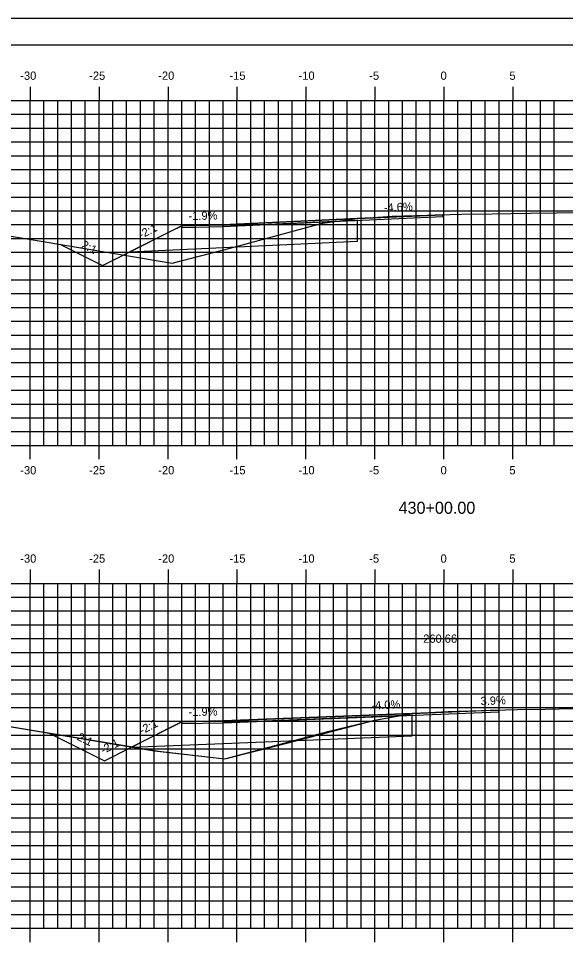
# Model space of a CAD drawing. Extents: x 1168600 to 1177589, y 610178 to 611246.
# Drawn here: x 1175598.1 to 1175637.7, y 610943.3 to 611010.5 of the extents above; entities that cross this region are included whole.
import ezdxf

# ---------------------------------------------------------------- set-up
doc = ezdxf.new("R2010")
doc.units = 0
for name, color, linetype in [('_Construction', 7, 'Continuous'), ('_Station Equation', 7, 'Continuous'), ('ANNOTATION', 7, 'Continuous'), ('D_Roadway_Centerline_Text', 7, 'Continuous'), ('D_Roadway_Edge_TW', 7, 'Continuous'), ('D_Roadway_SubGrade', 7, 'Continuous'), ('D_Slope_Direction', 7, 'Continuous'), ('D_Text_Standard', 7, 'Continuous'), ('H_V ANNOTATION', 7, 'Continuous'), ('MAJOR', 7, 'Continuous'), ('MATCH LINES', 7, 'Continuous'), ('MINOR', 7, 'Continuous')]:
    doc.layers.add(name, color=color, linetype=linetype)

msp = doc.modelspace()

# ---------------------------------------------------------------- linework, layer by layer
at = {"layer": '_Construction'}
msp.add_line((1175713.907, 611008.596), (1175553.907, 611008.596), dxfattribs=at)
msp.add_lwpolyline([(1175545.813, 610900.537), (1175715.813, 610900.537), (1175715.813, 611010.537), (1175545.813, 611010.537)], close=True, dxfattribs=at)
at = {"layer": '_Station Equation'}
for points in [[(1175558.906, 610999.472), (1175561.135, 610999.342), (1175570.673, 610998.545), (1175591.003, 610995.85), (1175598.702, 610994.577), (1175609.218, 610992.798), (1175613.404, 610993.903), (1175620.107, 610995.709), (1175622.451, 610996.017), (1175622.653, 610996.033), (1175623.778, 610996.113), (1175625.164, 610996.209), (1175627.75, 610996.287), (1175630.178, 610996.354), (1175632.416, 610996.39), (1175635.192, 610996.436), (1175637.081, 610996.46), (1175640.207, 610996.5)], [(1175558.906, 610999.472), (1175561.135, 610999.342), (1175570.437, 610998.097), (1175591.003, 610995.85), (1175598.703, 610994.577), (1175609.218, 610992.798), (1175613.404, 610993.903), (1175620.107, 610995.709), (1175622.452, 610996.017), (1175622.653, 610996.033), (1175623.777, 610996.113), (1175625.164, 610996.209), (1175627.749, 610996.287), (1175630.178, 610996.354), (1175632.415, 610996.39), (1175635.192, 610996.436), (1175637.08, 610996.46), (1175640.207, 610996.5)], [(1175558.906, 610963.059), (1175560.503, 610962.973), (1175582.409, 610961.101), (1175591.481, 610960.219), (1175608.214, 610957.43), (1175613.021, 610956.887), (1175617.624, 610958.04), (1175623.889, 610959.689), (1175626.561, 610960.16), (1175626.605, 610960.167), (1175626.71, 610960.174), (1175626.905, 610960.184), (1175629.22, 610960.311), (1175631.641, 610960.379), (1175634.239, 610960.45), (1175636.259, 610960.487), (1175639.258, 610960.542)], [(1175558.906, 610963.054), (1175560.503, 610962.973), (1175585.574, 610960.888), (1175591.481, 610960.219), (1175607.923, 610957.463), (1175613.021, 610956.887), (1175620.598, 610958.89), (1175623.888, 610959.689), (1175625.664, 610960.003), (1175626.563, 610960.16), (1175626.605, 610960.167), (1175626.71, 610960.174), (1175626.906, 610960.184), (1175629.22, 610960.311), (1175631.641, 610960.379), (1175634.239, 610960.45), (1175636.259, 610960.487), (1175639.258, 610960.542)]]:
    msp.add_lwpolyline(points, dxfattribs=at)
at = {"layer": 'D_Roadway_Edge_TW'}
for points in [[(1175628.834, 610996.317), (1175622.653, 610996.032), (1175612.906, 610995.577), (1175609.914, 610995.521), (1175609.914, 610995.396), (1175612.906, 610995.452), (1175628.834, 610996.192)], [(1175628.834, 610996.317), (1175622.653, 610996.032), (1175612.906, 610995.577), (1175609.914, 610995.521), (1175609.914, 610995.396), (1175612.906, 610995.452), (1175628.834, 610996.192)], [(1175632.882, 610960.413), (1175626.605, 610960.167), (1175612.906, 610959.623), (1175609.917, 610959.567), (1175609.917, 610959.442), (1175612.906, 610959.498), (1175632.882, 610960.288)], [(1175632.882, 610960.413), (1175626.605, 610960.167), (1175612.906, 610959.623), (1175609.917, 610959.567), (1175609.917, 610959.442), (1175612.906, 610959.498), (1175632.882, 610960.288)]]:
    msp.add_lwpolyline(points, close=True, dxfattribs=at)
for points in [[(1175628.834, 610996.317), (1175622.653, 610996.032), (1175612.906, 610995.577), (1175612.906, 610995.452), (1175628.834, 610996.192), (1175628.834, 610996.317)], [(1175628.834, 610996.317), (1175622.653, 610996.032), (1175612.906, 610995.577), (1175612.906, 610995.452), (1175628.834, 610996.192), (1175628.834, 610996.317)], [(1175632.882, 610960.413), (1175626.605, 610960.167), (1175612.906, 610959.623), (1175612.906, 610959.498), (1175632.882, 610960.288), (1175632.882, 610960.413)], [(1175632.882, 610960.413), (1175626.605, 610960.167), (1175612.906, 610959.623), (1175612.906, 610959.498), (1175632.882, 610960.288), (1175632.882, 610960.413)]]:
    msp.add_lwpolyline(points, dxfattribs=at)
at = {"layer": 'D_Roadway_SubGrade'}
for points in [[(1175612.906, 610995.577), (1175609.914, 610995.521), (1175606.143, 610993.635), (1175612.906, 610993.952), (1175622.653, 610994.407), (1175622.653, 610995.907), (1175612.906, 610995.452)], [(1175612.906, 610995.577), (1175609.914, 610995.521), (1175606.143, 610993.635), (1175612.906, 610993.952), (1175622.653, 610994.407), (1175622.653, 610995.907), (1175612.906, 610995.452)], [(1175612.906, 610959.623), (1175609.917, 610959.567), (1175606.25, 610957.731), (1175612.906, 610957.998), (1175626.605, 610958.542), (1175626.605, 610960.042), (1175612.906, 610959.498)], [(1175612.906, 610959.623), (1175609.917, 610959.567), (1175606.25, 610957.731), (1175612.906, 610957.998), (1175626.605, 610958.542), (1175626.605, 610960.042), (1175612.906, 610959.498)]]:
    msp.add_lwpolyline(points, close=True, dxfattribs=at)
at = {"layer": 'D_Slope_Direction'}
for points in [[(1175612.906, 610995.577), (1175609.914, 610995.521)], [(1175612.906, 610995.577), (1175609.914, 610995.521)], [(1175612.906, 610959.623), (1175609.917, 610959.567)], [(1175612.906, 610959.623), (1175609.917, 610959.567)]]:
    msp.add_lwpolyline(points, dxfattribs=at)
at = {"layer": 'D_Text_Standard'}
for points in [[(1175601.057, 610994.179), (1175604.144, 610992.635), (1175606.143, 610993.635), (1175609.12, 610995.124), (1175609.914, 610995.521), (1175612.761, 610995.574), (1175612.906, 610995.577), (1175613.337, 610995.597), (1175622.653, 610996.032), (1175627.171, 610996.24), (1175628.834, 610996.317)], [(1175600.29, 610958.742), (1175604.307, 610956.734), (1175606.25, 610957.731), (1175607.647, 610958.431), (1175609.917, 610959.567), (1175611.863, 610959.604), (1175612.906, 610959.623), (1175617.326, 610959.799), (1175626.605, 610960.167), (1175632.373, 610960.393), (1175632.882, 610960.413)]]:
    msp.add_lwpolyline(points, dxfattribs=at)
at = {"layer": 'MAJOR'}
for p, q in [((1175598.906, 611005.598), (1175598.906, 611004.596)), ((1175603.906, 611005.598), (1175603.906, 611004.596)), ((1175608.906, 611005.598), (1175608.906, 611004.596)), ((1175613.906, 611005.598), (1175613.906, 611004.596)), ((1175618.906, 611005.598), (1175618.906, 611004.596)), ((1175623.906, 611005.598), (1175623.906, 611004.596)), ((1175628.906, 611005.598), (1175628.906, 611004.596)), ((1175633.906, 611005.598), (1175633.906, 611004.596)), ((1175558.906, 611004.596), (1175698.906, 611004.596)), ((1175558.906, 611004.596), (1175698.906, 611004.596)), ((1175598.906, 610979.596), (1175598.906, 611004.596)), ((1175603.906, 610979.596), (1175603.906, 611004.596)), ((1175608.906, 610979.596), (1175608.906, 611004.596)), ((1175613.906, 610979.596), (1175613.906, 611004.596)), ((1175618.906, 610979.596), (1175618.906, 611004.596)), ((1175623.906, 610979.596), (1175623.906, 611004.596)), ((1175628.906, 610979.596), (1175628.906, 611004.596)), ((1175633.906, 610979.596), (1175633.906, 611004.596)), ((1175558.906, 610999.596), (1175698.906, 610999.596)), ((1175558.906, 610994.596), (1175698.906, 610994.596)), ((1175558.906, 610989.596), (1175698.906, 610989.596)), ((1175558.906, 610984.596), (1175698.906, 610984.596)), ((1175558.906, 610979.596), (1175698.906, 610979.596)), ((1175558.906, 610979.596), (1175698.906, 610979.596)), ((1175598.906, 610978.594), (1175598.906, 610979.596)), ((1175603.906, 610978.594), (1175603.906, 610979.596)), ((1175608.906, 610978.594), (1175608.906, 610979.596)), ((1175613.906, 610978.594), (1175613.906, 610979.596)), ((1175618.906, 610978.594), (1175618.906, 610979.596)), ((1175623.906, 610978.594), (1175623.906, 610979.596)), ((1175628.906, 610978.594), (1175628.906, 610979.596)), ((1175633.906, 610978.594), (1175633.906, 610979.596)), ((1175598.906, 610970.598), (1175598.906, 610969.596)), ((1175603.906, 610970.598), (1175603.906, 610969.596)), ((1175608.906, 610970.598), (1175608.906, 610969.596)), ((1175613.906, 610970.598), (1175613.906, 610969.596)), ((1175618.906, 610970.598), (1175618.906, 610969.596)), ((1175623.906, 610970.598), (1175623.906, 610969.596)), ((1175628.906, 610970.598), (1175628.906, 610969.596)), ((1175633.906, 610970.598), (1175633.906, 610969.596)), ((1175558.906, 610969.596), (1175698.906, 610969.596)), ((1175558.906, 610969.596), (1175698.906, 610969.596)), ((1175598.906, 610944.596), (1175598.906, 610969.596)), ((1175603.906, 610944.596), (1175603.906, 610969.596)), ((1175608.906, 610944.596), (1175608.906, 610969.596)), ((1175613.906, 610944.596), (1175613.906, 610969.596)), ((1175618.906, 610944.596), (1175618.906, 610969.596)), ((1175623.906, 610944.596), (1175623.906, 610969.596)), ((1175628.906, 610944.596), (1175628.906, 610969.596)), ((1175633.906, 610944.596), (1175633.906, 610969.596)), ((1175558.906, 610964.596), (1175698.906, 610964.596)), ((1175558.906, 610959.596), (1175698.906, 610959.596)), ((1175558.906, 610954.596), (1175698.906, 610954.596)), ((1175558.906, 610949.596), (1175698.906, 610949.596)), ((1175558.906, 610944.596), (1175698.906, 610944.596)), ((1175558.906, 610944.596), (1175698.906, 610944.596)), ((1175598.906, 610943.594), (1175598.906, 610944.596)), ((1175603.906, 610943.594), (1175603.906, 610944.596)), ((1175608.906, 610943.594), (1175608.906, 610944.596)), ((1175613.906, 610943.594), (1175613.906, 610944.596)), ((1175618.906, 610943.594), (1175618.906, 610944.596)), ((1175623.906, 610943.594), (1175623.906, 610944.596)), ((1175628.906, 610943.594), (1175628.906, 610944.596)), ((1175633.906, 610943.594), (1175633.906, 610944.596))]:
    msp.add_line(p, q, dxfattribs=at)
at = {"layer": 'MATCH LINES'}
for points in [[(1175612.906, 610995.577), (1175612.906, 610995.452)], [(1175612.906, 610995.577), (1175612.906, 610995.452)], [(1175612.906, 610959.623), (1175612.906, 610959.498)], [(1175612.906, 610959.623), (1175612.906, 610959.498)]]:
    msp.add_lwpolyline(points, dxfattribs=at)
at = {"layer": 'MINOR'}
for p, q in [((1175599.906, 610979.596), (1175599.906, 611004.596)), ((1175600.906, 610979.596), (1175600.906, 611004.596)), ((1175601.906, 610979.596), (1175601.906, 611004.596)), ((1175602.906, 610979.596), (1175602.906, 611004.596)), ((1175604.906, 610979.596), (1175604.906, 611004.596)), ((1175605.906, 610979.596), (1175605.906, 611004.596)), ((1175606.906, 610979.596), (1175606.906, 611004.596)), ((1175607.906, 610979.596), (1175607.906, 611004.596)), ((1175609.906, 610979.596), (1175609.906, 611004.596)), ((1175610.906, 610979.596), (1175610.906, 611004.596)), ((1175611.906, 610979.596), (1175611.906, 611004.596)), ((1175612.906, 610979.596), (1175612.906, 611004.596)), ((1175614.906, 610979.596), (1175614.906, 611004.596)), ((1175615.906, 610979.596), (1175615.906, 611004.596)), ((1175616.906, 610979.596), (1175616.906, 611004.596)), ((1175617.906, 610979.596), (1175617.906, 611004.596)), ((1175619.906, 610979.596), (1175619.906, 611004.596)), ((1175620.906, 610979.596), (1175620.906, 611004.596)), ((1175621.906, 610979.596), (1175621.906, 611004.596)), ((1175622.906, 610979.596), (1175622.906, 611004.596)), ((1175624.906, 610979.596), (1175624.906, 611004.596)), ((1175625.906, 610979.596), (1175625.906, 611004.596)), ((1175626.906, 610979.596), (1175626.906, 611004.596)), ((1175627.906, 610979.596), (1175627.906, 611004.596)), ((1175629.906, 610979.596), (1175629.906, 611004.596)), ((1175630.906, 610979.596), (1175630.906, 611004.596)), ((1175631.906, 610979.596), (1175631.906, 611004.596)), ((1175632.906, 610979.596), (1175632.906, 611004.596)), ((1175634.906, 610979.596), (1175634.906, 611004.596)), ((1175635.906, 610979.596), (1175635.906, 611004.596)), ((1175636.906, 610979.596), (1175636.906, 611004.596)), ((1175558.906, 611003.596), (1175698.906, 611003.596)), ((1175558.906, 611002.596), (1175698.906, 611002.596)), ((1175558.906, 611001.596), (1175698.906, 611001.596)), ((1175558.906, 611000.596), (1175698.906, 611000.596)), ((1175558.906, 610998.596), (1175698.906, 610998.596)), ((1175558.906, 610997.596), (1175698.906, 610997.596)), ((1175558.906, 610996.596), (1175698.906, 610996.596)), ((1175558.906, 610995.596), (1175698.906, 610995.596)), ((1175558.906, 610993.596), (1175698.906, 610993.596)), ((1175558.906, 610992.596), (1175698.906, 610992.596)), ((1175558.906, 610991.596), (1175698.906, 610991.596)), ((1175558.906, 610990.596), (1175698.906, 610990.596)), ((1175558.906, 610988.596), (1175698.906, 610988.596)), ((1175558.906, 610987.596), (1175698.906, 610987.596)), ((1175558.906, 610986.596), (1175698.906, 610986.596)), ((1175558.906, 610985.596), (1175698.906, 610985.596)), ((1175558.906, 610983.596), (1175698.906, 610983.596)), ((1175558.906, 610982.596), (1175698.906, 610982.596)), ((1175558.906, 610981.596), (1175698.906, 610981.596)), ((1175558.906, 610980.596), (1175698.906, 610980.596)), ((1175599.906, 610944.596), (1175599.906, 610969.596)), ((1175600.906, 610944.596), (1175600.906, 610969.596)), ((1175601.906, 610944.596), (1175601.906, 610969.596)), ((1175602.906, 610944.596), (1175602.906, 610969.596)), ((1175604.906, 610944.596), (1175604.906, 610969.596)), ((1175605.906, 610944.596), (1175605.906, 610969.596)), ((1175606.906, 610944.596), (1175606.906, 610969.596)), ((1175607.906, 610944.596), (1175607.906, 610969.596)), ((1175609.906, 610944.596), (1175609.906, 610969.596)), ((1175610.906, 610944.596), (1175610.906, 610969.596)), ((1175611.906, 610944.596), (1175611.906, 610969.596)), ((1175612.906, 610944.596), (1175612.906, 610969.596)), ((1175614.906, 610944.596), (1175614.906, 610969.596)), ((1175615.906, 610944.596), (1175615.906, 610969.596)), ((1175616.906, 610944.596), (1175616.906, 610969.596)), ((1175617.906, 610944.596), (1175617.906, 610969.596)), ((1175619.906, 610944.596), (1175619.906, 610969.596)), ((1175620.906, 610944.596), (1175620.906, 610969.596)), ((1175621.906, 610944.596), (1175621.906, 610969.596)), ((1175622.906, 610944.596), (1175622.906, 610969.596)), ((1175624.906, 610944.596), (1175624.906, 610969.596)), ((1175625.906, 610944.596), (1175625.906, 610969.596)), ((1175626.906, 610944.596), (1175626.906, 610969.596)), ((1175627.906, 610944.596), (1175627.906, 610969.596)), ((1175629.906, 610944.596), (1175629.906, 610969.596)), ((1175630.906, 610944.596), (1175630.906, 610969.596)), ((1175631.906, 610944.596), (1175631.906, 610969.596)), ((1175632.906, 610944.596), (1175632.906, 610969.596)), ((1175634.906, 610944.596), (1175634.906, 610969.596)), ((1175635.906, 610944.596), (1175635.906, 610969.596)), ((1175636.906, 610944.596), (1175636.906, 610969.596)), ((1175558.906, 610968.596), (1175698.906, 610968.596)), ((1175558.906, 610967.596), (1175698.906, 610967.596)), ((1175558.906, 610966.596), (1175698.906, 610966.596)), ((1175558.906, 610965.596), (1175698.906, 610965.596)), ((1175558.906, 610963.596), (1175698.906, 610963.596)), ((1175558.906, 610962.596), (1175698.906, 610962.596)), ((1175558.906, 610961.596), (1175698.906, 610961.596)), ((1175558.906, 610960.596), (1175698.906, 610960.596)), ((1175558.906, 610958.596), (1175698.906, 610958.596)), ((1175558.906, 610957.596), (1175698.906, 610957.596)), ((1175558.906, 610956.596), (1175698.906, 610956.596)), ((1175558.906, 610955.596), (1175698.906, 610955.596)), ((1175558.906, 610953.596), (1175698.906, 610953.596)), ((1175558.906, 610952.596), (1175698.906, 610952.596)), ((1175558.906, 610951.596), (1175698.906, 610951.596)), ((1175558.906, 610950.596), (1175698.906, 610950.596)), ((1175558.906, 610948.596), (1175698.906, 610948.596)), ((1175558.906, 610947.596), (1175698.906, 610947.596)), ((1175558.906, 610946.596), (1175698.906, 610946.596)), ((1175558.906, 610945.596), (1175698.906, 610945.596))]:
    msp.add_line(p, q, dxfattribs=at)

# ---------------------------------------------------------------- texts
at = {"layer": 'ANNOTATION'}
for s, rotation, p in [('-4.6%', 2.63741, (1175624.564, 610996.522)), ('-1.9%', 1.07154, (1175610.397, 610995.93)), ('-2:1', 26.56661, (1175606.958, 610994.561)), ('2:1', 333.43495, (1175602.568, 610993.942)), ('-4.0%', 2.26023, (1175623.666, 610960.45)), ('3.9%', 2.26142, (1175631.578, 610960.763)), ('-1.9%', 1.07289, (1175610.398, 610959.976)), ('-2:1', 26.59525, (1175607.012, 610958.631)), ('2:1', 333.43495, (1175602.265, 610958.272)), ('-2:1', 27.17394, (1175604.201, 610957.204))]:
    msp.add_text(s, height=0.6, rotation=rotation, dxfattribs=at).set_placement(p)
at = {"layer": 'D_Roadway_Centerline_Text'}
msp.add_text('260.66', height=0.6, dxfattribs=at).set_placement((1175627.408, 610965.289))
at = {"layer": 'H_V ANNOTATION'}
for s, height, p in [('-30', 0.6, (1175598.195, 611006.096)), ('-25', 0.6, (1175603.192, 611006.096)), ('-20', 0.6, (1175608.2, 611006.096)), ('-15', 0.6, (1175613.363, 611006.096)), ('-10', 0.6, (1175618.371, 611006.096)), ('-5', 0.6, (1175623.497, 611006.096)), ('0', 0.6, (1175628.665, 611006.096)), ('5', 0.6, (1175633.657, 611006.096)), ('-30', 0.6, (1175598.195, 610977.496)), ('-25', 0.6, (1175603.192, 610977.496)), ('-20', 0.6, (1175608.2, 610977.496)), ('-15', 0.6, (1175613.363, 610977.496)), ('-10', 0.6, (1175618.371, 610977.496)), ('-5', 0.6, (1175623.497, 610977.496)), ('0', 0.6, (1175628.665, 610977.496)), ('5', 0.6, (1175633.657, 610977.496)), ('430+00.00', 0.875, (1175625.621, 610974.639)), ('-30', 0.6, (1175598.195, 610971.096)), ('-25', 0.6, (1175603.192, 610971.096)), ('-20', 0.6, (1175608.2, 610971.096)), ('-15', 0.6, (1175613.363, 610971.096)), ('-10', 0.6, (1175618.371, 610971.096)), ('-5', 0.6, (1175623.497, 610971.096)), ('0', 0.6, (1175628.665, 610971.096)), ('5', 0.6, (1175633.657, 610971.096))]:
    msp.add_text(s, height=height, dxfattribs=at).set_placement(p)

doc.saveas('drawing.dxf')
